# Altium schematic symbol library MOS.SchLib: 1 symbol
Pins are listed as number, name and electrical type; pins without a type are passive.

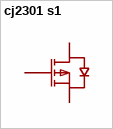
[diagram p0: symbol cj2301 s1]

## cj2301 s1
designator Q??  (value not drawn)
数量:1个P沟道;漏源电压(Vdss):20V;连续漏极电流(Id):2.3A;导通电阻(RDS(on)):142mΩ@2.5V;耗散功率(Pd):350mW;阈值电压(Vgs(th)):1V;; Manufacturer: CJ(江苏长电/长晶); AddInBom: yes; ModelId: 89cb27a44ab2466697082bb9fd73a7d0; ModelName: SOT-23-3L_L2.9-W1.6-H1.1-LS2.8-P0.95; ModelTransform: 114.173,110.236,0,90,0,0,0,0,0; Number: 1个P沟道; Drain to Source Voltage: 20V; Current - Continuous Drain(Id): 2.3A; Pd - Power Dissipation: 350mW; Gate Threshold Voltage (Vgs(th)): 1V; Gate Charge(Qg): 5.5nC; Input Capacitance(Ciss): 405pF; Reverse Transfer Capacitance (Crss@Vds): 55pF; Type: P沟道; Output Capacitance(Coss): 75pF; Vgs: ±8V
footprint SOT-23-3_L3.0-W1.7-P0.95-LS2.9-BR
pins: 1 G, 2 S, 3 D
